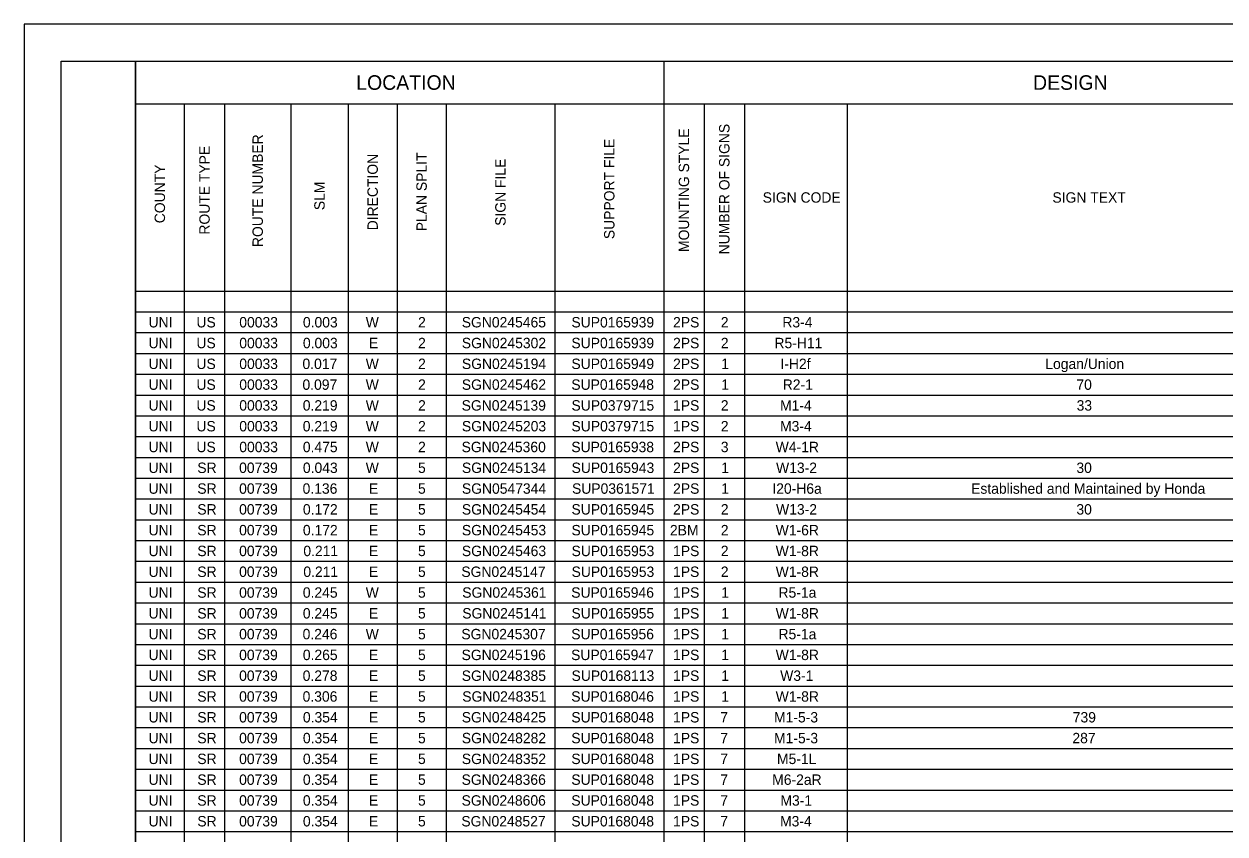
# Model space of a CAD drawing. Extents: x 0 to 34, y 0 to 22.
# Drawn here: x 0 to 16.17, y 11.09 to 22 of the extents above; entities that cross this region are included whole.
import ezdxf

# ---------------------------------------------------------------- set-up
doc = ezdxf.new("R2010")
doc.units = 0
for name, color, linetype in [('Default', 7, 'Continuous'), ('SH_Border', 7, 'Continuous'), ('SH_Cut_Line', 7, 'Continuous'), ('SH_Data', 7, 'Continuous')]:
    doc.layers.add(name, color=color, linetype=linetype)

msp = doc.modelspace()

# ---------------------------------------------------------------- linework, layer by layer
at = {"layer": 'SH_Border'}
for points in [[(0.5, 21.5), (1.5, 21.5), (1.5, 0.5), (0.5, 0.5)], [(1.5, 21.5), (33.5, 21.5), (33.5, 0.5), (1.5, 0.5)]]:
    msp.add_lwpolyline(points, close=True, dxfattribs=at)
at = {"layer": 'SH_Cut_Line'}
msp.add_lwpolyline([(0, 0), (34, 0), (34, 22), (0, 22)], close=True, dxfattribs=at)
at = {"layer": 'SH_Data'}
for p, q in [((1.5, 21.5), (32.004, 21.5)), ((8.615, 21.5), (8.615, 0.764)), ((1.5, 20.924), (28.232, 20.924)), ((1.5, 20.924), (1.5, 0.764)), ((2.159, 20.924), (2.159, 0.764)), ((2.702, 20.924), (2.702, 0.764)), ((3.592, 20.924), (3.592, 0.764)), ((4.366, 20.924), (4.366, 0.764)), ((5.025, 20.924), (5.025, 0.764)), ((5.684, 20.924), (5.684, 0.764)), ((7.149, 20.924), (7.149, 0.764)), ((9.159, 20.924), (9.159, 0.764)), ((9.702, 20.924), (9.702, 0.764)), ((11.086, 20.924), (11.086, 0.764)), ((1.5, 18.404), (32.004, 18.404)), ((1.5, 18.124), (32.004, 18.124)), ((1.5, 17.844), (32.004, 17.844)), ((1.5, 17.564), (32.004, 17.564)), ((1.5, 17.284), (32.004, 17.284)), ((1.5, 17.004), (32.004, 17.004)), ((1.5, 16.724), (32.004, 16.724)), ((1.5, 16.444), (32.004, 16.444)), ((1.5, 16.164), (32.004, 16.164)), ((1.5, 15.884), (32.004, 15.884)), ((1.5, 15.604), (32.004, 15.604)), ((1.5, 15.324), (32.004, 15.324)), ((1.5, 15.044), (32.004, 15.044)), ((1.5, 14.764), (32.004, 14.764)), ((1.5, 14.484), (32.004, 14.484)), ((1.5, 14.204), (32.004, 14.204)), ((1.5, 13.924), (32.004, 13.924)), ((1.5, 13.644), (32.004, 13.644)), ((1.5, 13.364), (32.004, 13.364)), ((1.5, 13.084), (32.004, 13.084)), ((1.5, 12.804), (32.004, 12.804)), ((1.5, 12.524), (32.004, 12.524)), ((1.5, 12.244), (32.004, 12.244)), ((1.5, 11.964), (32.004, 11.964)), ((1.5, 11.684), (32.004, 11.684)), ((1.5, 11.404), (32.004, 11.404)), ((1.5, 11.124), (32.004, 11.124))]:
    msp.add_line(p, q, dxfattribs=at)

# ---------------------------------------------------------------- texts
at = {"layer": 'Default'}
for s, height, p in [('LOCATION', 0.196, (4.474, 21.114)), ('DESIGN', 0.196, (13.589, 21.114)), ('SIGN CODE', 0.14, (9.948, 19.594)), ('SIGN TEXT', 0.14, (13.85, 19.594)), ('UNI', 0.14, (1.677, 17.914)), ('US', 0.14, (2.322, 17.914)), ('00033', 0.14, (2.899, 17.914)), ('0.003', 0.14, (3.756, 17.914)), ('W', 0.14, (4.602, 17.914)), ('2', 0.14, (5.307, 17.914)), ('SGN0245465', 0.14, (5.895, 17.914)), ('SUP0165939', 0.14, (7.372, 17.914)), ('2PS', 0.14, (8.741, 17.914)), ('2', 0.14, (9.384, 17.914)), ('R3-4', 0.14, (10.213, 17.914)), ('UNI', 0.14, (1.677, 17.634)), ('US', 0.14, (2.322, 17.634)), ('00033', 0.14, (2.899, 17.634)), ('0.003', 0.14, (3.756, 17.634)), ('E', 0.14, (4.645, 17.634)), ('2', 0.14, (5.307, 17.634)), ('SGN0245302', 0.14, (5.896, 17.634)), ('SUP0165939', 0.14, (7.372, 17.634)), ('2PS', 0.14, (8.741, 17.634)), ('2', 0.14, (9.384, 17.634)), ('R5-H11', 0.14, (10.106, 17.634)), ('UNI', 0.14, (1.677, 17.354)), ('US', 0.14, (2.322, 17.354)), ('00033', 0.14, (2.899, 17.354)), ('0.017', 0.14, (3.75, 17.354)), ('W', 0.14, (4.602, 17.354)), ('2', 0.14, (5.307, 17.354)), ('SGN0245194', 0.14, (5.897, 17.354)), ('SUP0165949', 0.14, (7.372, 17.354)), ('2PS', 0.14, (8.741, 17.354)), ('1', 0.14, (9.389, 17.354)), ('I-H2f', 0.14, (10.187, 17.354)), ('Logan/Union', 0.14, (13.754, 17.354)), ('UNI', 0.14, (1.677, 17.074)), ('US', 0.14, (2.322, 17.074)), ('00033', 0.14, (2.899, 17.074)), ('0.097', 0.14, (3.75, 17.074)), ('W', 0.14, (4.602, 17.074)), ('2', 0.14, (5.307, 17.074)), ('SGN0245462', 0.14, (5.896, 17.074)), ('SUP0165948', 0.14, (7.371, 17.074)), ('2PS', 0.14, (8.741, 17.074)), ('1', 0.14, (9.389, 17.074)), ('R2-1', 0.14, (10.218, 17.074)), ('70', 0.14, (14.173, 17.074)), ('UNI', 0.14, (1.677, 16.794)), ('US', 0.14, (2.322, 16.794)), ('00033', 0.14, (2.899, 16.794)), ('0.219', 0.14, (3.754, 16.794)), ('W', 0.14, (4.602, 16.794)), ('2', 0.14, (5.307, 16.794)), ('SGN0245139', 0.14, (5.894, 16.794)), ('SUP0379715', 0.14, (7.373, 16.794)), ('1PS', 0.14, (8.741, 16.794)), ('2', 0.14, (9.384, 16.794)), ('M1-4', 0.14, (10.182, 16.794)), ('33', 0.14, (14.176, 16.794)), ('UNI', 0.14, (1.677, 16.514)), ('US', 0.14, (2.322, 16.514)), ('00033', 0.14, (2.899, 16.514)), ('0.219', 0.14, (3.754, 16.514)), ('W', 0.14, (4.602, 16.514)), ('2', 0.14, (5.307, 16.514)), ('SGN0245203', 0.14, (5.897, 16.514)), ('SUP0379715', 0.14, (7.373, 16.514)), ('1PS', 0.14, (8.741, 16.514)), ('2', 0.14, (9.384, 16.514)), ('M3-4', 0.14, (10.182, 16.514)), ('UNI', 0.14, (1.677, 16.234)), ('US', 0.14, (2.322, 16.234)), ('00033', 0.14, (2.899, 16.234)), ('0.475', 0.14, (3.755, 16.234)), ('W', 0.14, (4.602, 16.234)), ('2', 0.14, (5.307, 16.234)), ('SGN0245360', 0.14, (5.893, 16.234)), ('SUP0165938', 0.14, (7.371, 16.234)), ('2PS', 0.14, (8.741, 16.234)), ('3', 0.14, (9.384, 16.234)), ('W4-1R', 0.14, (10.123, 16.234)), ('UNI', 0.14, (1.677, 15.954)), ('SR', 0.14, (2.334, 15.954)), ('00739', 0.14, (2.897, 15.954)), ('0.043', 0.14, (3.756, 15.954)), ('W', 0.14, (4.602, 15.954)), ('5', 0.14, (5.306, 15.954)), ('SGN0245134', 0.14, (5.897, 15.954)), ('SUP0165943', 0.14, (7.374, 15.954)), ('2PS', 0.14, (8.741, 15.954)), ('1', 0.14, (9.389, 15.954)), ('W13-2', 0.14, (10.128, 15.954)), ('30', 0.14, (14.173, 15.954)), ('UNI', 0.14, (1.677, 15.674)), ('SR', 0.14, (2.334, 15.674)), ('00739', 0.14, (2.897, 15.674)), ('0.136', 0.14, (3.752, 15.674)), ('E', 0.14, (4.645, 15.674)), ('5', 0.14, (5.306, 15.674)), ('SGN0547344', 0.14, (5.897, 15.674)), ('SUP0361571', 0.14, (7.38, 15.674)), ('2PS', 0.14, (8.741, 15.674)), ('1', 0.14, (9.389, 15.674)), ('I20-H6a', 0.14, (10.078, 15.674)), ('Established and Maintained by Honda', 0.14, (12.755, 15.674)), ('UNI', 0.14, (1.677, 15.394)), ('SR', 0.14, (2.334, 15.394)), ('00739', 0.14, (2.897, 15.394)), ('0.172', 0.14, (3.756, 15.394)), ('E', 0.14, (4.645, 15.394)), ('5', 0.14, (5.306, 15.394)), ('SGN0245454', 0.14, (5.897, 15.394)), ('SUP0165945', 0.14, (7.373, 15.394)), ('2PS', 0.14, (8.741, 15.394)), ('2', 0.14, (9.384, 15.394)), ('W13-2', 0.14, (10.128, 15.394)), ('30', 0.14, (14.173, 15.394)), ('UNI', 0.14, (1.677, 15.114)), ('SR', 0.14, (2.334, 15.114)), ('00739', 0.14, (2.897, 15.114)), ('0.172', 0.14, (3.756, 15.114)), ('E', 0.14, (4.645, 15.114)), ('5', 0.14, (5.306, 15.114)), ('SGN0245453', 0.14, (5.897, 15.114)), ('SUP0165945', 0.14, (7.373, 15.114)), ('2BM', 0.14, (8.699, 15.114)), ('2', 0.14, (9.384, 15.114)), ('W1-6R', 0.14, (10.123, 15.114)), ('UNI', 0.14, (1.677, 14.834)), ('SR', 0.14, (2.334, 14.834)), ('00739', 0.14, (2.897, 14.834)), ('0.211', 0.14, (3.762, 14.834)), ('E', 0.14, (4.645, 14.834)), ('5', 0.14, (5.306, 14.834)), ('SGN0245463', 0.14, (5.897, 14.834)), ('SUP0165953', 0.14, (7.374, 14.834)), ('1PS', 0.14, (8.741, 14.834)), ('2', 0.14, (9.384, 14.834)), ('W1-8R', 0.14, (10.123, 14.834)), ('UNI', 0.14, (1.677, 14.554)), ('SR', 0.14, (2.334, 14.554)), ('00739', 0.14, (2.897, 14.554)), ('0.211', 0.14, (3.762, 14.554)), ('E', 0.14, (4.645, 14.554)), ('5', 0.14, (5.306, 14.554)), ('SGN0245147', 0.14, (5.89, 14.554)), ('SUP0165953', 0.14, (7.374, 14.554)), ('1PS', 0.14, (8.741, 14.554)), ('2', 0.14, (9.384, 14.554)), ('W1-8R', 0.14, (10.123, 14.554)), ('UNI', 0.14, (1.677, 14.274)), ('SR', 0.14, (2.334, 14.274)), ('00739', 0.14, (2.897, 14.274)), ('0.245', 0.14, (3.755, 14.274)), ('W', 0.14, (4.602, 14.274)), ('5', 0.14, (5.306, 14.274)), ('SGN0245361', 0.14, (5.902, 14.274)), ('SUP0165946', 0.14, (7.37, 14.274)), ('1PS', 0.14, (8.741, 14.274)), ('1', 0.14, (9.389, 14.274)), ('R5-1a', 0.14, (10.161, 14.274)), ('UNI', 0.14, (1.677, 13.994)), ('SR', 0.14, (2.334, 13.994)), ('00739', 0.14, (2.897, 13.994)), ('0.245', 0.14, (3.755, 13.994)), ('E', 0.14, (4.645, 13.994)), ('5', 0.14, (5.306, 13.994)), ('SGN0245141', 0.14, (5.902, 13.994)), ('SUP0165955', 0.14, (7.373, 13.994)), ('1PS', 0.14, (8.741, 13.994)), ('1', 0.14, (9.389, 13.994)), ('W1-8R', 0.14, (10.123, 13.994)), ('UNI', 0.14, (1.677, 13.714)), ('SR', 0.14, (2.334, 13.714)), ('00739', 0.14, (2.897, 13.714)), ('0.246', 0.14, (3.752, 13.714)), ('W', 0.14, (4.602, 13.714)), ('5', 0.14, (5.306, 13.714)), ('SGN0245307', 0.14, (5.89, 13.714)), ('SUP0165956', 0.14, (7.37, 13.714)), ('1PS', 0.14, (8.741, 13.714)), ('1', 0.14, (9.389, 13.714)), ('R5-1a', 0.14, (10.161, 13.714)), ('UNI', 0.14, (1.677, 13.434)), ('SR', 0.14, (2.334, 13.434)), ('00739', 0.14, (2.897, 13.434)), ('0.265', 0.14, (3.755, 13.434)), ('E', 0.14, (4.645, 13.434)), ('5', 0.14, (5.306, 13.434)), ('SGN0245196', 0.14, (5.893, 13.434)), ('SUP0165947', 0.14, (7.368, 13.434)), ('1PS', 0.14, (8.741, 13.434)), ('1', 0.14, (9.389, 13.434)), ('W1-8R', 0.14, (10.123, 13.434)), ('UNI', 0.14, (1.677, 13.154)), ('SR', 0.14, (2.334, 13.154)), ('00739', 0.14, (2.897, 13.154)), ('0.278', 0.14, (3.753, 13.154)), ('E', 0.14, (4.645, 13.154)), ('5', 0.14, (5.306, 13.154)), ('SGN0248385', 0.14, (5.895, 13.154)), ('SUP0168113', 0.14, (7.374, 13.154)), ('1PS', 0.14, (8.741, 13.154)), ('1', 0.14, (9.389, 13.154)), ('W3-1', 0.14, (10.184, 13.154)), ('UNI', 0.14, (1.677, 12.874)), ('SR', 0.14, (2.334, 12.874)), ('00739', 0.14, (2.897, 12.874)), ('0.306', 0.14, (3.752, 12.874)), ('E', 0.14, (4.645, 12.874)), ('5', 0.14, (5.306, 12.874)), ('SGN0248351', 0.14, (5.902, 12.874)), ('SUP0168046', 0.14, (7.37, 12.874)), ('1PS', 0.14, (8.741, 12.874)), ('1', 0.14, (9.389, 12.874)), ('W1-8R', 0.14, (10.123, 12.874)), ('UNI', 0.14, (1.677, 12.594)), ('SR', 0.14, (2.334, 12.594)), ('00739', 0.14, (2.897, 12.594)), ('0.354', 0.14, (3.756, 12.594)), ('E', 0.14, (4.645, 12.594)), ('5', 0.14, (5.306, 12.594)), ('SGN0248425', 0.14, (5.895, 12.594)), ('SUP0168048', 0.14, (7.371, 12.594)), ('1PS', 0.14, (8.741, 12.594)), ('7', 0.14, (9.377, 12.594)), ('M1-5-3', 0.14, (10.101, 12.594)), ('739', 0.14, (14.124, 12.594)), ('SR', 0.14, (2.334, 12.314)), ('00739', 0.14, (2.897, 12.314)), ('0.354', 0.14, (3.756, 12.314)), ('SGN0248282', 0.14, (5.896, 12.314)), ('SUP0168048', 0.14, (7.371, 12.314)), ('1PS', 0.14, (8.741, 12.314)), ('M1-5-3', 0.14, (10.101, 12.314)), ('287', 0.14, (14.119, 12.314)), ('UNI', 0.14, (1.677, 12.314)), ('E', 0.14, (4.645, 12.314)), ('5', 0.14, (5.306, 12.314)), ('7', 0.14, (9.377, 12.314)), ('UNI', 0.14, (1.677, 12.034)), ('SR', 0.14, (2.334, 12.034)), ('00739', 0.14, (2.897, 12.034)), ('0.354', 0.14, (3.756, 12.034)), ('E', 0.14, (4.645, 12.034)), ('5', 0.14, (5.306, 12.034)), ('SGN0248352', 0.14, (5.896, 12.034)), ('SUP0168048', 0.14, (7.371, 12.034)), ('1PS', 0.14, (8.741, 12.034)), ('7', 0.14, (9.377, 12.034)), ('M5-1L', 0.14, (10.141, 12.034)), ('UNI', 0.14, (1.677, 11.754)), ('SR', 0.14, (2.334, 11.754)), ('00739', 0.14, (2.897, 11.754)), ('0.354', 0.14, (3.756, 11.754)), ('E', 0.14, (4.645, 11.754)), ('5', 0.14, (5.306, 11.754)), ('SGN0248366', 0.14, (5.893, 11.754)), ('SUP0168048', 0.14, (7.371, 11.754)), ('1PS', 0.14, (8.741, 11.754)), ('7', 0.14, (9.377, 11.754)), ('M6-2aR', 0.14, (10.076, 11.754)), ('UNI', 0.14, (1.677, 11.474)), ('SR', 0.14, (2.334, 11.474)), ('00739', 0.14, (2.897, 11.474)), ('0.354', 0.14, (3.756, 11.474)), ('E', 0.14, (4.645, 11.474)), ('5', 0.14, (5.306, 11.474)), ('SGN0248606', 0.14, (5.893, 11.474)), ('SUP0168048', 0.14, (7.371, 11.474)), ('1PS', 0.14, (8.741, 11.474)), ('7', 0.14, (9.377, 11.474)), ('M3-1', 0.14, (10.187, 11.474)), ('UNI', 0.14, (1.677, 11.194)), ('SR', 0.14, (2.334, 11.194)), ('00739', 0.14, (2.897, 11.194)), ('0.354', 0.14, (3.756, 11.194)), ('E', 0.14, (4.645, 11.194)), ('5', 0.14, (5.306, 11.194)), ('SGN0248527', 0.14, (5.89, 11.194)), ('SUP0168048', 0.14, (7.371, 11.194)), ('1PS', 0.14, (8.741, 11.194)), ('7', 0.14, (9.377, 11.194)), ('M3-4', 0.14, (10.182, 11.194))]:
    msp.add_text(s, height=height, dxfattribs=at).set_placement(p)
for s, p in [('MOUNTING STYLE', (8.957, 18.93)), ('NUMBER OF SIGNS', (9.501, 18.898)), ('ROUTE NUMBER', (3.217, 18.996)), ('SUPPORT FILE', (7.952, 19.103)), ('ROUTE TYPE', (2.501, 19.164)), ('DIRECTION', (4.765, 19.222)), ('PLAN SPLIT', (5.424, 19.209)), ('COUNTY', (1.899, 19.317)), ('SIGN FILE', (6.486, 19.282)), ('SLM', (4.049, 19.493))]:
    msp.add_text(s, height=0.14, rotation=90, dxfattribs=at).set_placement(p)

doc.saveas('drawing.dxf')
